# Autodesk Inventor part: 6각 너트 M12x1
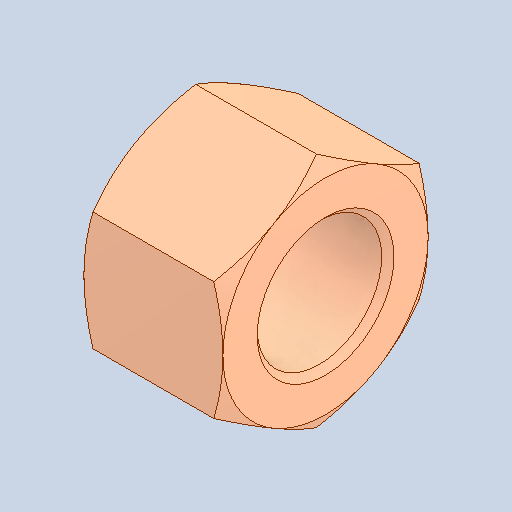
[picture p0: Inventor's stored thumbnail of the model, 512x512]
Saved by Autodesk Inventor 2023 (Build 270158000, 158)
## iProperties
Created: 2026-06
Part Number: 6각 너트 M12x1
Material: 강철, 연강
Description: 6각 너트 및 6각 가는 너트
Document SubType Name: Modeling
Designer: 4강의실
Density: 7.85 g/cm^3
Appearance: 기본값
Author: jhkim
Sending System: Autodesk Inventor 2027
Preprocessor: ST-DEVELOPER v20.1
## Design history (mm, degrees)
feature "Solid1"
node "솔리드1"
